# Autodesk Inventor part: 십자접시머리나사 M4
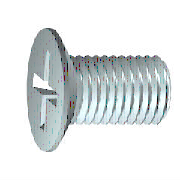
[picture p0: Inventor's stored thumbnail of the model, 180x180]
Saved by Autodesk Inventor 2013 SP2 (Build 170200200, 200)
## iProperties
IsCustomPart: 0
Created: 2012-02
Part Number: 십자접시머리나사 M4
Material: 강철, 연강
Description: 십자 오목 머리 나사
Document SubType Name: Modeling
Standard: KS B 1023
Designer: mduedu
Standards Organization: KS
Language: ko-KR
Size Designation: A  M 4 x 12 - H
Categories: <MemberInstance><Categories><Category DisplayName="조임쇠" InternalName="e4da775c-781d-43d5-af7c-5136215cf5a6" Mnemonic="FSTN"><Category DisplayName="볼트" InternalN
Density: 7.86 g/cm^3
Mass: 1.50482 g
Surface Area: 2.78557 cm^2
Volume: 0.191453 cm^3
Author: mduedu
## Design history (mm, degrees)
body "Solid1"
sketch "스케치1"
  geometry: L1 (2.6, 0)-(12, 0); L2 (12, 0)-(12, 2); L3 (12, 2)-(4.1, 2); L4 (4.1, 2)-(3.671, 1.785); L5 (3.671, 1.785)-(2.7, 1.785); L6 (0, 4.2)-(0, 2.4); L7 (0, 2.4)-(1.801, 1.502); L8 (1.801, 1.502)-(2.6, 0); L9 (-2.4, 0)-(14.4, 0) reference; L10 (0, -0.84)-(0, 5.04) reference; L11 (0, 4.2)-(0.285, 4.2); L12 (0.285, 4.2)-(2.7, 1.785); L13 (4.1, 2)-(2.485, 2)
  constraints: 22 end point, 3 parallel, 3 perpendicular, 2 collinear, 1 horizontal, 1 point on line
  dimensions: "d1" = 7.9 distance of L2.end L3.end (= GEL); "d2" = 4 diameter of L3 L1 (= GD); "d3" = 3.57058 diameter of L5 L1 (= BDM); "d4" = 4.8 diameter of L6.end L1 (= SDM); "d5" = 26.5 deg angle of L7 L1; "d6" = 62 deg angle of L8 L1; "d7" = 2.6 distance from line of L1.start L6 (= INTI); "d8" = 0.42941 horizontal distance of L4.end L3.end (= GAL); "d12" = 8.4 diameter of L11 L1 (= KOD); "d13" = 45 deg angle of L12 L1 (= 0.5 x SEWI); "d15" = 12 distance between parallel lines of L2 L6 (= NLG); "d24" = 2.7 distance from line of L5.end L6 (= KOH)
revolve "본체" stored, may be unused: angle "d16" = 90 deg
sketch "스케치2"
  geometry: L1 (0, 2.4)-(0, 0); L2 (0, 0)-(2.4, 0); L3 (0, 0)-(1.697, 1.697); L4 (0.312, 2.38)-(0.408, 0.734); L5 (2.38, 0.312)-(0.734, 0.408); L6 (0, -5.88)-(0, 5.88) reference; L7 (-5.88, 0)-(5.88, 0) reference; L8 (2.38, -0.312)-(0.734, -0.408); L9 (0.312, -2.38)-(0.408, -0.734); L10 (-0.312, -2.38)-(-0.408, -0.734); L11 (-2.38, -0.312)-(-0.734, -0.408); L12 (-2.38, 0.312)-(-0.734, 0.408); L13 (-0.312, 2.38)-(-0.408, 0.734); A1 r 0.72 centre (0, 0) between (0.72, 0) and (0, 0.72); A2 r 0.84 centre (0, 0) between (0.84, 0) and (0, 0.84); A3 r 2.4 centre (0, 0) between (2.38, 0.312) and (0.312, 2.38); A4 r 2.4 centre (0, 0) between (0.312, 2.38) and (0, 2.4); A5 r 2.4 centre (0, 0) between (2.4, 0) and (2.38, 0.312); A6 r 2.4 centre (0, 0) between (0, -2.4) and (0.312, -2.38); A7 r 2.4 centre (0, 0) between (0.312, -2.38) and (2.38, -0.312); A8 r 2.4 centre (0, 0) between (2.38, -0.312) and (2.4, 0); A9 r 2.4 centre (0, 0) between (0, 2.4) and (-0.312, 2.38); A10 r 2.4 centre (0, 0) between (-0.312, 2.38) and (-2.38, 0.312); A11 r 2.4 centre (0, 0) between (-2.38, 0.312) and (-2.4, 0); A12 r 2.4 centre (0, 0) between (-2.4, 0) and (-2.38, -0.312); A13 r 2.4 centre (0, 0) between (-2.38, -0.312) and (-0.312, -2.38); A14 r 2.4 centre (0, 0) between (-0.312, -2.38) and (0, -2.4); A15 r 0.347 centre (0.755, 0.755) between (0.408, 0.734) and (0.734, 0.408); A16 r 0.347 centre (0.755, -0.755) between (0.734, -0.408) and (0.408, -0.734); A17 r 0.347 centre (-0.755, -0.755) between (-0.408, -0.734) and (-0.734, -0.408); A18 r 0.347 centre (-0.755, 0.755) between (-0.734, 0.408) and (-0.408, 0.734); 3 further points
  constraints: 41 point on circle, 22 end point, 22 symmetric about line, 18 centre point, 11 coincident, 4 point on line, 3 tangent, 2 collinear, 1 perpendicular, 1 vertical, 19 other
  dimensions: "d17" = 1.44 diameter of A1 (= 0.3 x SDM); "d18" = 1.68 diameter of A2 (= 0.35 x SDM); "d19" = 4.8 diameter of A3 (= SDM); "d20" = 45 deg angle of L3 L2; "d21" = 0.3115 distance from line of L4.start L1 (= 0.5 x SBR)
extrude "슬롯" join sketch "스케치2" taper "d22" = 5 deg; stored distance "d79" = 25.4
fillet "모깎기1" dims "d23" = 0.1246 (= 0.2 x SBR)
feature "스레드" dims "d10" = 7.9 (= GEL), "d11" = 0
chamfer "모따기1" distance "d25" = 0.42941 (= -0.5 x SPD + 0.5 x GD); stored, may be unused: second distance "d26" = 0.21471 (= 0.5 x GAL), angle "d88" = 45 deg
workplane "Work Plane2"
other parameters: "NLG" = 12 [user parameter; used in 1 equation term], "GEL" = 7.9 [user parameter; used in 2 equation terms], "GAL" = 0.42941 (= 0.61345 x PTC) [user parameter; used in 3 equation terms], "SPD" = 3.14117 (= NND - 1.2269 x PTC) [user parameter; used in 1 equation term], "KOD" = 8.4 [user parameter; used in 1 equation term], "KOH" = 2.7 [user parameter; used in 1 equation term], "SBR" = 0.623 [user parameter; used in 2 equation terms], "INTI" = 2.6 [user parameter; used in 1 equation term], "SDM" = 4.8 [user parameter; used in 5 equation terms], "GD" = 4 (= NND) [user parameter; used in 2 equation terms], "BDM" = 3.57058 (= NND - GAL) [user parameter; used in 1 equation term], "SEWI" = 90 deg [user parameter; used in 1 equation term], "d9" = 4.8 (= SDM), "d27" = 0, "d91" = 0, "d92" = 0, "GUL" = 0.42941 (= 0.61345 x PTC) [user parameter], "TOA" = 30 deg [user parameter], "EPV" = 4.7 [user parameter], "THREADDIA" = 4 [user parameter; used in 1 equation term], "TPU" = 14.28571 (computed from PTC) [user parameter], "PTC" = 0.7 [user parameter; used in 5 equation terms], "NND" = 4 [user parameter; used in 3 equation terms], "GD1" = 3.14117 (= THREADDIA - 1.2269 x PTC) [user parameter]
